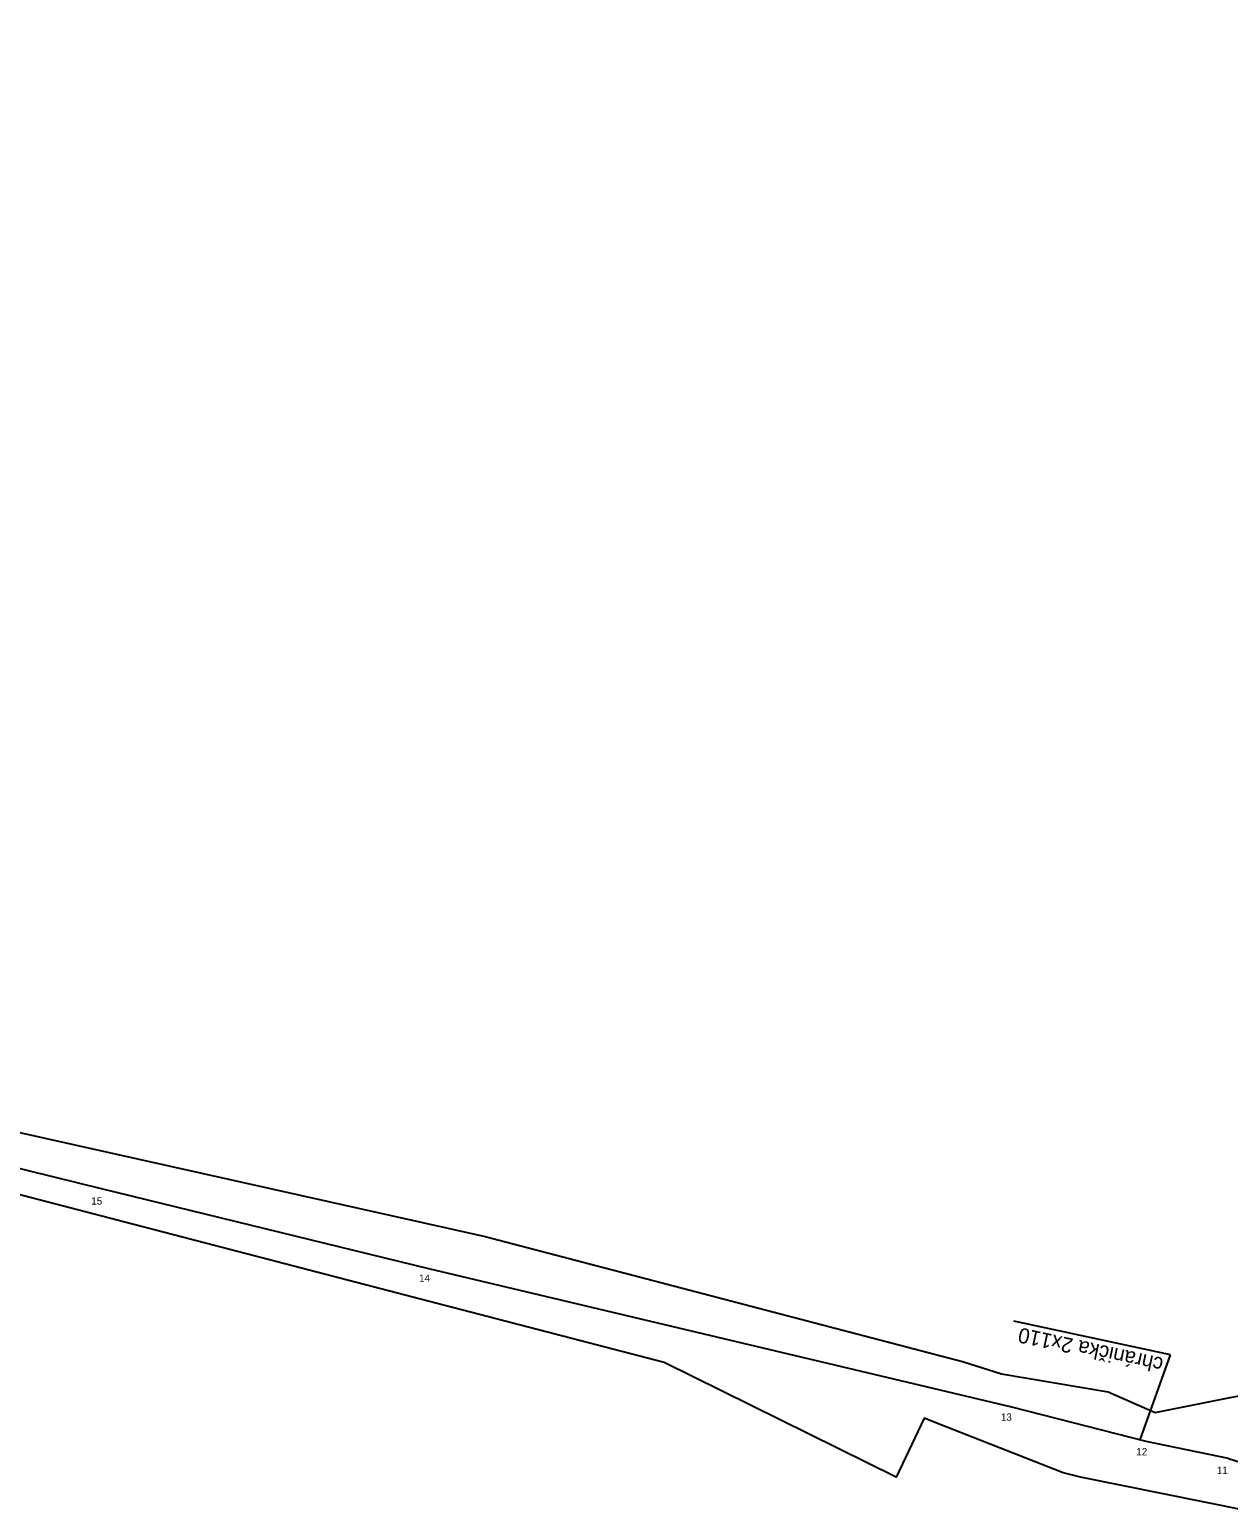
# Model space of a CAD drawing. Extents: x -748344 to -743169, y -1131966 to -1127091.
# Drawn here: x -747497.5 to -747299.4, y -1131782.9 to -1131538.2 of the extents above; entities that cross this region are included whole.
import ezdxf

# ---------------------------------------------------------------- set-up
doc = ezdxf.new("R2010")
doc.units = 0
for name, color, linetype in [('_Zabezpečovací zařízení_trasa', 7, 'Continuous'), ('křížky', 7, 'Continuous'), ('Nový stav', 7, 'Continuous'), ('Vrstva 53', 7, 'Continuous'), ('Vrstva 60', 7, 'Continuous')]:
    doc.layers.add(name, color=color, linetype=linetype)

# ---------------------------------------------------------------- blocks, each defined once
blk = doc.blocks.new('POINT_DISPLAY')
blk.add_line((0, 0), (0, 0))

msp = doc.modelspace()

# ---------------------------------------------------------------- linework, layer by layer
at = {"layer": '_Zabezpečovací zařízení_trasa'}
msp.add_lwpolyline([(-747299.39, -1131774.36), (-747312.96, -1131771.54), (-747335.19, -1131765.86), (-747431.5, -1131743.03), (-747485.59, -1131729.82), (-747529.87, -1131718.9), (-747616.75, -1131698.31), (-747822.02, -1131648.41), (-747861.48, -1131639.04), (-748013.3, -1131602), (-748116.9, -1131577.08), (-748210.22, -1131554.48), (-748277.3, -1131538.23)], dxfattribs=at)
msp.add_arc((-747264.33, -1131667.72), 112.26, 251.8015, 269.7738, dxfattribs=at)
at = {"layer": 'Nový stav'}
for p, q in [((-747308.93, -1131757.22), (-747334.86, -1131751.66)), ((-747313.94, -1131771.29), (-747308.93, -1131757.22))]:
    msp.add_line(p, q, dxfattribs=at)
at = {"layer": 'Vrstva 53'}
for points in [[(-747515.95, -1131716.72), (-747422.18, -1131737.69), (-747343.31, -1131758.31), (-747336.85, -1131760.37), (-747319.28, -1131763.36), (-747311.5, -1131766.78), (-747286.37, -1131761.74)], [(-747296.48, -1131782.93), (-747323.8, -1131777.42), (-747326.7, -1131776.72), (-747346.48, -1131768.98), (-747349.64, -1131767.7), (-747354.27, -1131777.45), (-747392.64, -1131758.47), (-747431.62, -1131748.34), (-747522.4, -1131724.74)]]:
    msp.add_lwpolyline(points, dxfattribs=at)
at = {"layer": 'Vrstva 60'}
for p, q in [((-747485.59, -1131729.82), (-747485.59, -1131729.82)), ((-747431.5, -1131743.03), (-747431.5, -1131743.03)), ((-747335.19, -1131765.86), (-747335.19, -1131765.86)), ((-747312.96, -1131771.54), (-747312.96, -1131771.54))]:
    msp.add_line(p, q, dxfattribs=at)

# ---------------------------------------------------------------- block references
at = {"layer": 'křížky', "xscale": 10, "yscale": 10, "rotation": 61.14491455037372}
for p in [(-747485.59, -1131729.82), (-747431.5, -1131743.03), (-747335.19, -1131765.86), (-747312.96, -1131771.54), (-747299.39, -1131774.36)]:
    msp.add_blockref('POINT_DISPLAY', p, dxfattribs=at)

# ---------------------------------------------------------------- texts
at = {"layer": 'Nový stav'}
msp.add_text('chránička 2x110', height=2.5, rotation=167.8986, dxfattribs=at).set_placement((-747309.99, -1131757.78))
at = {"layer": 'Vrstva 60'}
for s, p in [('15', (-747487.26, -1131732.4)), ('14', (-747433.1, -1131745.15)), ('13', (-747336.97, -1131768.11)), ('12', (-747314.59, -1131773.83)), ('11', (-747301.29, -1131776.91))]:
    msp.add_text(s, height=1.2, dxfattribs=at).set_placement(p)

doc.saveas('drawing.dxf')
